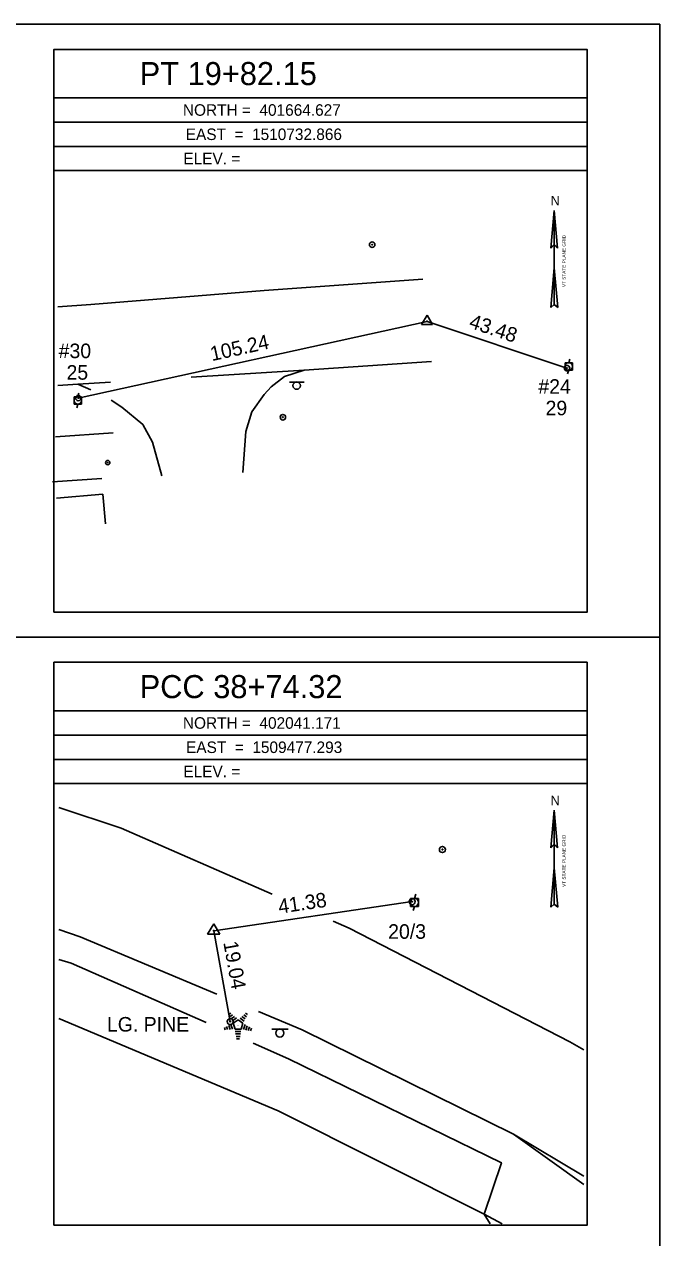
# Model space of a CAD drawing. Extents: x 1508412 to 1509054, y 401108 to 401963.
# Drawn here: x 1508920.8 to 1509051.9, y 401277.6 to 401527.7 of the extents above; entities that cross this region are included whole.
import ezdxf

# ---------------------------------------------------------------- set-up
doc = ezdxf.new("R2010")
doc.units = 0
for name, color, linetype in [('CBP', 7, 'Continuous'), ('CPH', 7, 'Continuous'), ('Default', 7, 'Continuous'), ('L_C', 7, 'Continuous'), ('LAWA', 7, 'Continuous'), ('LBC', 7, 'Continuous'), ('LFNC', 7, 'Continuous'), ('LTC', 7, 'Continuous'), ('LWS', 7, 'Continuous'), ('MPIP', 7, 'Continuous'), ('MPIR', 7, 'Continuous'), ('NBL1', 7, 'Continuous'), ('NBL2', 7, 'Continuous'), ('NNA_P', 7, 'Continuous'), ('PET', 7, 'Continuous'), ('RDP', 7, 'Continuous'), ('SSGN', 7, 'Continuous'), ('U_C', 7, 'Continuous'), ('UP', 7, 'Continuous'), ('UPGW', 7, 'Continuous')]:
    doc.layers.add(name, color=color, linetype=linetype)

msp = doc.modelspace()

# ---------------------------------------------------------------- linework, layer by layer
at = {"layer": 'CBP'}
for centre, radius in [((1509032.77, 401456.84), 0.569), ((1509032.77, 401456.84), 0.0758), ((1508931.95, 401450.69), 0.569), ((1508931.95, 401450.69), 0.0758), ((1509000.83, 401346.9), 0.625), ((1509000.83, 401346.9), 0.0833), ((1508963.28, 401322.18), 0.625), ((1508963.28, 401322.18), 0.0833)]:
    msp.add_circle(centre, radius, dxfattribs=at)
at = {"layer": 'CPH'}
for p, q in [((1509002.76, 401465.83), (1509003.9, 401467.8)), ((1509005.04, 401465.83), (1509003.9, 401467.8)), ((1509003.9, 401466.49), (1509003.9, 401466.49)), ((1509002.76, 401465.83), (1509005.04, 401465.83)), ((1508958.63, 401340.19), (1508959.88, 401342.35)), ((1508961.13, 401340.19), (1508959.88, 401342.35)), ((1508958.63, 401340.19), (1508961.13, 401340.19)), ((1508959.89, 401340.91), (1508959.89, 401340.91))]:
    msp.add_line(p, q, dxfattribs=at)
for centre, radius in [((1509003.9, 401466.49), 0.0758), ((1508959.89, 401340.91), 0.0833)]:
    msp.add_circle(centre, radius, dxfattribs=at)
at = {"layer": 'Default'}
for p, q in [((1508931.95, 401450.69), (1509003.9, 401466.49)), ((1509003.9, 401466.49), (1509032.77, 401456.84)), ((1508959.89, 401340.91), (1509000.83, 401346.9)), ((1508963.28, 401322.18), (1508959.89, 401340.91))]:
    msp.add_line(p, q, dxfattribs=at)
at = {"layer": 'LAWA'}
for points in [[(1508927.91, 401335), (1508930.46, 401334.19), (1508958.31, 401321.97)], [(1508968.04, 401317.7), (1508975.28, 401314.52), (1509019.23, 401293.09), (1509015.69, 401282.51), (1509016.91, 401280.48)]]:
    msp.add_lwpolyline(points, dxfattribs=at)
at = {"layer": 'LBC'}
for points in [[(1508937, 401430.89), (1508927.48, 401430.03)], [(1508937.57, 401424.79), (1508937, 401430.89)]]:
    msp.add_lwpolyline(points, dxfattribs=at)
at = {"layer": 'LFNC'}
for points in [[(1508927.25, 401442.68), (1508939.16, 401443.55)], [(1508926.64, 401433.44), (1508936.82, 401434.12)]]:
    msp.add_lwpolyline(points, dxfattribs=at)
at = {"layer": 'LTC'}
for p, q in [((1508963.05, 401323.68), (1508963.41, 401323.94)), ((1508966.45, 401323.92), (1508966.87, 401323.62)), ((1508963, 401321.4), (1508963.27, 401320.56)), ((1508963.26, 401323.22), (1508963.79, 401323.6)), ((1508963.45, 401321.61), (1508963.78, 401320.59)), ((1508963.47, 401322.75), (1508964.18, 401323.26)), ((1508963.68, 401322.29), (1508964.56, 401322.93)), ((1508963.91, 401321.83), (1508964.92, 401322.57)), ((1508963.91, 401321.83), (1508964.29, 401320.64)), ((1508964.92, 401322.57), (1508965.91, 401321.84)), ((1508965.34, 401322.88), (1508966.15, 401322.29)), ((1508965.91, 401321.84), (1508965.52, 401320.64)), ((1508965.71, 401323.23), (1508966.39, 401322.73)), ((1508966.35, 401321.57), (1508966.01, 401320.53)), ((1508966.08, 401323.58), (1508966.63, 401323.18)), ((1508966.8, 401321.32), (1508966.51, 401320.44)), ((1508962.09, 401320.96), (1508962.24, 401320.5)), ((1508962.54, 401321.18), (1508962.75, 401320.53)), ((1508965.52, 401320.64), (1508964.29, 401320.64)), ((1508965.49, 401320.14), (1508964.34, 401320.14)), ((1508965.4, 401319.64), (1508964.41, 401319.64)), ((1508965.32, 401319.14), (1508964.49, 401319.14)), ((1508967.24, 401321.07), (1508967, 401320.34)), ((1508967.69, 401320.82), (1508967.5, 401320.25)), ((1508965.23, 401318.64), (1508964.56, 401318.64))]:
    msp.add_line(p, q, dxfattribs=at)
at = {"layer": 'LWS'}
for points in [[(1508973.16, 401303.78), (1508927.91, 401322.83)], [(1508973.16, 401303.78), (1509015.69, 401282.51)], [(1509019.39, 401280.48), (1509015.69, 401282.51)]]:
    msp.add_lwpolyline(points, dxfattribs=at)
at = {"layer": 'MPIP'}
for radius in [0.569, 0.0758]:
    msp.add_circle((1508974.16, 401446.73), radius, dxfattribs=at)
at = {"layer": 'MPIR'}
for radius in [0.569, 0.0758]:
    msp.add_circle((1508992.58, 401482.29), radius, dxfattribs=at)
at = {"layer": 'NBL1'}
msp.add_lwpolyline([(1508411.91, 401107.72), (1509051.91, 401107.72), (1509051.91, 401527.72), (1508411.91, 401527.72)], close=True, dxfattribs=at)
at = {"layer": 'NBL2'}
for p, q in [((1509036.91, 401512.55), (1508926.91, 401512.55)), ((1509036.91, 401507.55), (1508926.91, 401507.55)), ((1509036.91, 401502.55), (1508926.91, 401502.55)), ((1509036.91, 401497.55), (1508926.91, 401497.55)), ((1508411.91, 401401.38), (1509051.91, 401401.38)), ((1509036.91, 401386.22), (1508926.91, 401386.22)), ((1509036.91, 401381.22), (1508926.91, 401381.22)), ((1509036.91, 401376.22), (1508926.91, 401376.22)), ((1509036.91, 401371.22), (1508926.91, 401371.22))]:
    msp.add_line(p, q, dxfattribs=at)
for points in [[(1508926.91, 401406.55), (1509036.91, 401406.55), (1509036.91, 401522.55), (1508926.91, 401522.55)], [(1508926.91, 401280.22), (1509036.91, 401280.22), (1509036.91, 401396.22), (1508926.91, 401396.22)]]:
    msp.add_lwpolyline(points, close=True, dxfattribs=at)
at = {"layer": 'NNA_P'}
for p, q in [((1509029.45, 401481.58), (1509030.15, 401489.37)), ((1509030.15, 401469.99), (1509030.15, 401489.37)), ((1509030.84, 401481.58), (1509030.15, 401489.37)), ((1509029.45, 401481.58), (1509030.15, 401482.34)), ((1509030.84, 401481.58), (1509030.15, 401482.34)), ((1509030.15, 401477.52), (1509029.43, 401469.35)), ((1509030.15, 401477.52), (1509030.87, 401469.35)), ((1509030.15, 401469.99), (1509029.43, 401469.35)), ((1509030.15, 401469.99), (1509030.87, 401469.35)), ((1509029.45, 401357.96), (1509030.15, 401365.75)), ((1509030.15, 401346.37), (1509030.15, 401365.75)), ((1509030.84, 401357.96), (1509030.15, 401365.75)), ((1509029.45, 401357.96), (1509030.15, 401358.72)), ((1509030.84, 401357.96), (1509030.15, 401358.72)), ((1509030.15, 401353.9), (1509029.43, 401345.73)), ((1509030.15, 401353.9), (1509030.87, 401345.73)), ((1509030.15, 401346.37), (1509029.43, 401345.73)), ((1509030.15, 401346.37), (1509030.87, 401345.73))]:
    msp.add_line(p, q, dxfattribs=at)
at = {"layer": 'PET'}
for points in [[(1508927.73, 401469.51), (1508934.54, 401469.97), (1508970.3, 401472.88), (1509003.04, 401475.17)], [(1508955.2, 401454.99), (1508978.57, 401456.45), (1509004.81, 401458.24)], [(1508978.57, 401456.45), (1508974.48, 401455.1), (1508971.72, 401452.97), (1508970.26, 401451.42), (1508967.73, 401447.87), (1508966.54, 401443.78), (1508965.9, 401435.37)], [(1508927.75, 401453.3), (1508931.83, 401453.54), (1508938.58, 401453.96)], [(1508931.83, 401453.54), (1508934.56, 401452.41)], [(1508938.76, 401450.22), (1508940.95, 401448.84), (1508945.25, 401445.23), (1508947.23, 401441.57), (1508949.18, 401434.67)], [(1508927.91, 401366.29), (1508940.81, 401362.03), (1508971.92, 401348.42)], [(1508984.55, 401342.89), (1508987.84, 401341.45), (1509033.36, 401318.04), (1509036.23, 401316.38)], [(1508927.91, 401341.14), (1508932.32, 401339.65), (1508960.54, 401327.83)], [(1508969.13, 401324.23), (1508978.14, 401320.46), (1509021.75, 401298.97), (1509036.23, 401290.3)]]:
    msp.add_lwpolyline(points, dxfattribs=at)
at = {"layer": 'RDP'}
msp.add_lwpolyline([(1509021.75, 401298.97), (1509036.23, 401288.63)], dxfattribs=at)
at = {"layer": 'SSGN'}
for p, q in [((1508975.5, 401453.99), (1508978.53, 401453.99)), ((1508977, 401453.24), (1508977, 401453.24)), ((1508971.88, 401320.65), (1508975.22, 401320.65)), ((1508973.53, 401319.82), (1508973.53, 401319.82))]:
    msp.add_line(p, q, dxfattribs=at)
for centre, radius in [((1508977, 401453.24), 0.758), ((1508973.53, 401319.82), 0.833)]:
    msp.add_circle(centre, radius, dxfattribs=at)
at = {"layer": 'UP'}
for p, q in [((1509032.36, 401456.46), (1509032.36, 401457.97)), ((1509032.36, 401457.97), (1509033.88, 401457.97)), ((1509033.88, 401456.46), (1509032.36, 401456.46)), ((1509032.89, 401455.7), (1509033.12, 401456.46)), ((1509033.35, 401458.73), (1509033.12, 401457.97)), ((1509033.12, 401457.22), (1509033.12, 401457.22)), ((1509033.88, 401457.97), (1509033.88, 401456.46)), ((1508932.07, 401451.71), (1508931.85, 401450.95)), ((1508931.09, 401449.44), (1508931.09, 401450.95)), ((1508931.09, 401450.95), (1508932.6, 401450.95)), ((1508932.6, 401449.44), (1508931.09, 401449.44)), ((1508931.62, 401448.68), (1508931.85, 401449.44)), ((1508931.85, 401450.19), (1508931.85, 401450.19)), ((1508932.6, 401450.95), (1508932.6, 401449.44)), ((1509000.47, 401345.91), (1509000.47, 401347.58)), ((1509000.47, 401347.58), (1509002.13, 401347.58)), ((1509001.55, 401348.41), (1509001.3, 401347.58)), ((1509001.3, 401346.75), (1509001.3, 401346.75)), ((1509002.13, 401347.58), (1509002.13, 401345.91)), ((1509002.13, 401345.91), (1509000.47, 401345.91)), ((1509001.05, 401345.08), (1509001.3, 401345.91))]:
    msp.add_line(p, q, dxfattribs=at)
for centre, radius in [((1509033.12, 401457.22), 0.758), ((1508931.85, 401450.19), 0.758), ((1509001.3, 401346.75), 0.833)]:
    msp.add_circle(centre, radius, dxfattribs=at)
at = {"layer": 'UPGW'}
for centre, radius in [((1508938.03, 401437.39), 0.437), ((1508938.03, 401437.39), 0.0583), ((1509007.07, 401357.64), 0.625), ((1509007.07, 401357.64), 0.0833)]:
    msp.add_circle(centre, radius, dxfattribs=at)

# ---------------------------------------------------------------- texts
at = {"layer": 'Default'}
for s, rotation, p in [('43.48', 341.517, (1509012.37, 401465.24)), ('105.24', 12.3841, (1508959.52, 401458.28)), ('41.38', 8.3285, (1508973.42, 401344.41)), ('19.04', 280.2849, (1508961.85, 401338.49))]:
    msp.add_text(s, height=3, rotation=rotation, dxfattribs=at).set_placement(p)
at = {"layer": 'L_C'}
msp.add_text('LG. PINE', height=3, dxfattribs=at).set_placement((1508937.86, 401320.12))
at = {"layer": 'LTC'}
msp.add_text('.', height=1.04, rotation=270, dxfattribs=at).set_placement((1508964.8, 401321.58))
at = {"layer": 'NBL2'}
for s, height, p in [('    PT 19+82.15    ', 4.75, (1508937.55, 401515.18)), ('NORTH =  401664.627 ', 2.375, (1508953.53, 401508.86)), ('EAST  =  1510732.866', 2.375, (1508954.12, 401503.86)), ('ELEV. =             ', 2.375, (1508953.63, 401498.86)), ('    PCC 38+74.32   ', 4.75, (1508937.55, 401388.84)), ('NORTH =  402041.171 ', 2.375, (1508953.53, 401382.53)), ('EAST  =  1509477.293', 2.375, (1508954.18, 401377.53)), ('ELEV. =             ', 2.375, (1508953.63, 401372.53))]:
    msp.add_text(s, height=height, dxfattribs=at).set_placement(p)
at = {"layer": 'NNA_P'}
for p in [(1509029.39, 401490.38), (1509029.39, 401366.76)]:
    msp.add_text('N', height=1.97, dxfattribs=at).set_placement(p)
for p in [(1509032.5, 401473.56), (1509032.5, 401349.94)]:
    msp.add_text('VT STATE PLANE GRID', height=0.7, rotation=90.0204, dxfattribs=at).set_placement(p)
at = {"layer": 'U_C'}
for s, p in [('#30', (1508927.9, 401458.91)), ('25', (1508929.52, 401454.47)), ('#24', (1509026.87, 401451.57)), ('29', (1509028.35, 401447.13)), ('20/3', (1508995.88, 401339.24))]:
    msp.add_text(s, height=3, dxfattribs=at).set_placement(p)

doc.saveas('drawing.dxf')
